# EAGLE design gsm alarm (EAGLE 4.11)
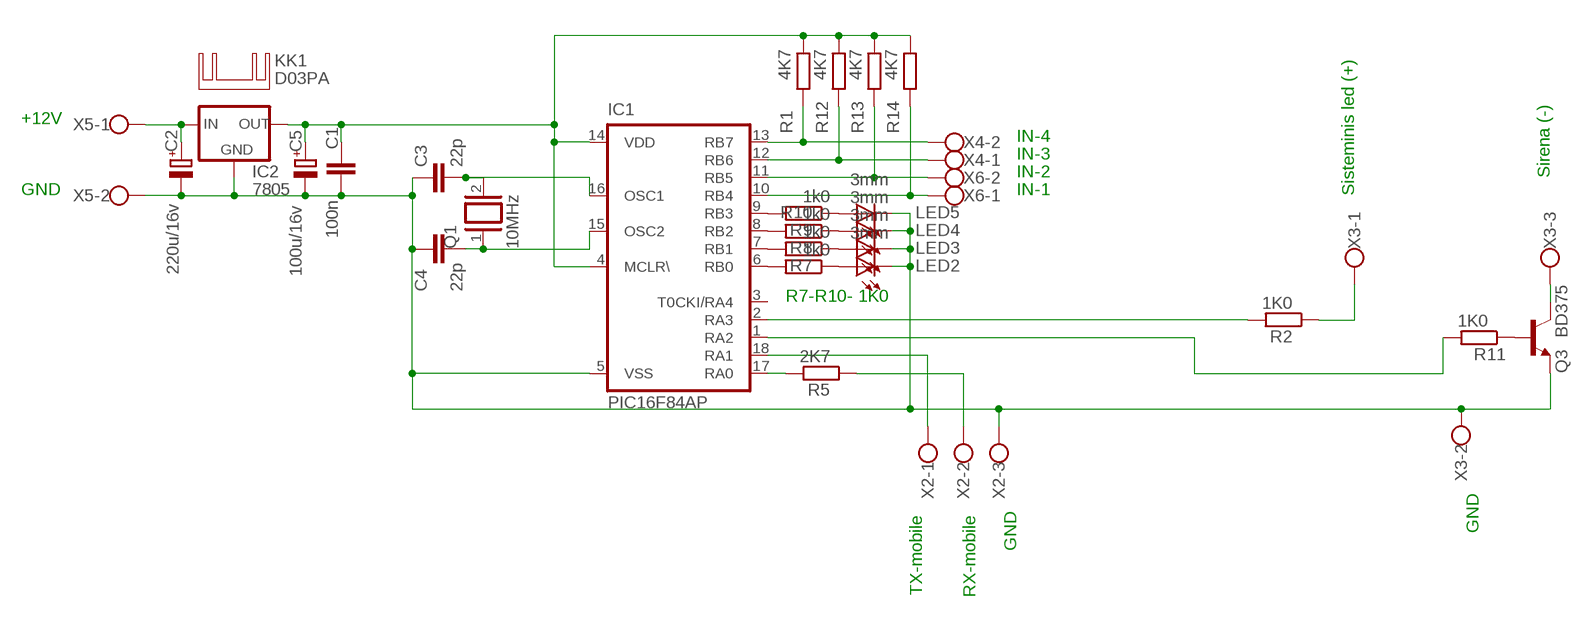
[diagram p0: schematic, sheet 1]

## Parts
C1  100n  C-EU050-045X075  [C050-045X075]
C2  220u/16v  CPOL-EUE5-10.5  [E5-10,5]
C3  22p  C-EU050-030X075  [C050-030X075]
C4  22p  C-EU050-030X075  [C050-030X075]
C5  100u/16v  CPOL-EUE5-10.5  [E5-10,5]
IC1  PIC16F84AP  [DIL18]
IC2  7805  78XXS  [78XXS]
KK1  D03PA  [D03PA]
LED2  3mm  LED3MM  [LED3MM]
LED3  3mm  LED3MM  [LED3MM]
LED4  3mm  LED3MM  [LED3MM]
LED5  3mm  LED3MM  [LED3MM]
Q1  10MHz  XTAL  [Q]
Q3  BD375  BD139  [TO126]
R1  4K7  R-EU_0207/2V  [0207/2V]
R2  1K0  R-EU_0204/7  [0204/7]
R5  2K7  R-EU_0204/7  [0204/7]
R7  1k0  R-EU_0204/7  [0204/7]
R8  1k0  R-EU_0204/7  [0204/7]
R9  1k0  R-EU_0204/7  [0204/7]
R10  1k0  R-EU_0204/7  [0204/7]
R11  1K0  R-EU_0204/7  [0204/7]
R12  4K7  R-EU_0207/2V  [0207/2V]
R13  4K7  R-EU_0207/2V  [0207/2V]
R14  4K7  R-EU_0207/2V  [0207/2V]
X2  AK300/3  [AK300/3]
X3  AK300/3  [AK300/3]
X4  AK300/2  [AK300/2]
X5  AK300/2  [AK300/2]
X6  AK300/2  [AK300/2]

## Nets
N$1: IC1.18(RA1) X2.1
N$2: R5.1 X2.2
N$3: IC1.13(RB7) R1.1 X4.2
N$4: Q3.3(B) R11.1
N$5: IC1.12(RB6) R12.1 X4.1
N$6: C1.1 C5.+ IC1.4(MCLR\) IC1.14(VDD) IC2.OUT R1.2 R12.2 R13.2 R14.2
N$7: IC1.11(RB5) R13.1 X6.2
N$8: R2.1 X3.1
N$9: Q3.2(C) X3.3
N$10: IC1.10(RB4) R14.1 X6.1
N$11: IC1.2(RA3) R2.2
N$12: IC1.6(RB0) R7.2
N$13: IC1.7(RB1) R8.2
N$14: IC1.8(RB2) R9.2
N$15: IC1.9(RB3) R10.2
N$16: LED2.A R7.1
N$17: C3.2 IC1.16(OSC1) Q1.2
N$18: C4.2 IC1.15(OSC2) Q1.1
N$21: C2.+ IC2.IN X5.1
N$28: LED3.A R8.1
N$29: C1.2 C2.- C3.1 C4.1 C5.- IC1.5(VSS) IC2.GND LED2.K(C) LED3.K(C) LED4.K(C) LED5.K(C) Q3.1(E) X2.3 X3.2 X5.2
N$30: LED4.A R9.1
N$31: LED5.A R10.1
N$34: IC1.1(RA2) R11.2
N$70: IC1.17(RA0) R5.2
Unconnected: IC1.3(T0CKI/RA4)

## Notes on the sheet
- +12V
- IN-4
- IN-3
- IN-2 | Sirena (-)
- GND | IN-1 | Sisteminis led (+)
- R7-R10- 1K0
- TX-mobile | RX-mobile
- GND
- GND

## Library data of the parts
C1 C3 C4 = rcl:C-EU: CAPACITOR, European symbol
C2 C5 = rcl:CPOL-EU: POLARIZED CAPACITOR, European symbol
IC1 = microchip:PIC16F8*: MICROCONTROLLER 8-Bit PIC16F8X Family - CMOS Flash/EEPROM Pin Compatible : PIC16F83, PIC16CR83, PIC16F84A, PIC16CR84 see also PIC16C*
IC2 = v-reg:78XXS: VOLTAGE REGULATOR
KK1 = heatsink:D03PA: HEATSINK
LED2-LED5 = led:LED: LED
Q1 = special:XTAL: CRYSTAL
Q3 = transistor-npn:BD139*: NPN Transistor
R1 R2 R5 R7-R14 = rcl:R-EU_: RESISTOR, European symbol
X2 X3 = con-ptr500+:AK300/3: CONNECTOR
X4-X6 = con-ptr500+:AK300/2: CONNECTOR

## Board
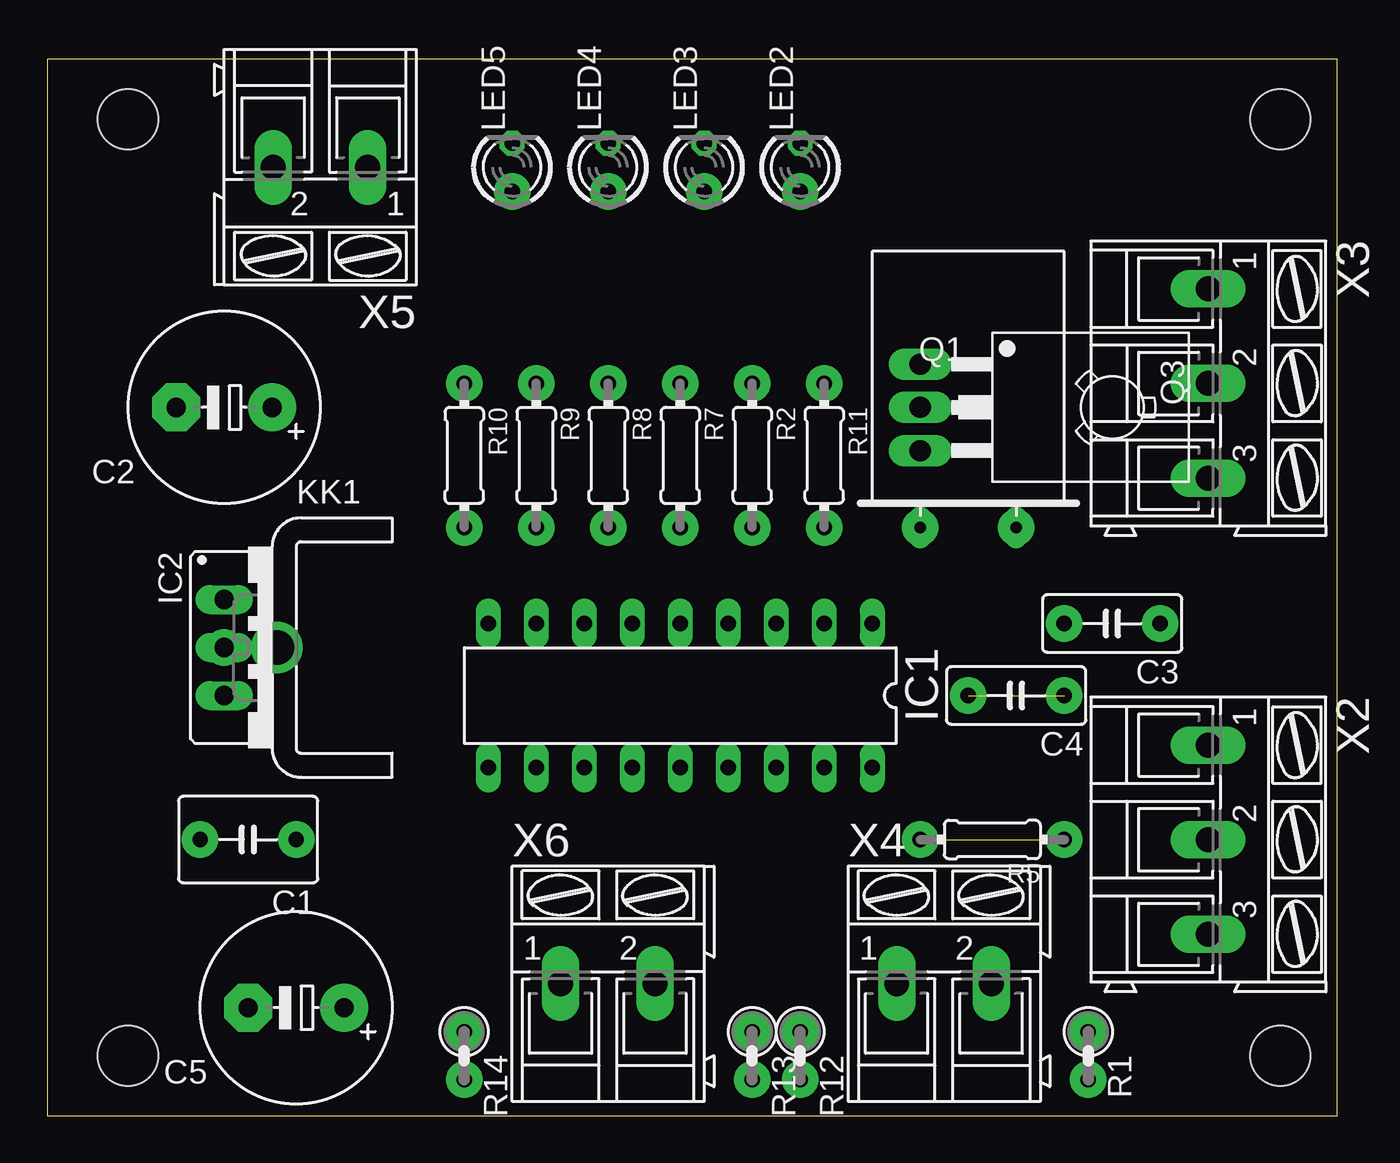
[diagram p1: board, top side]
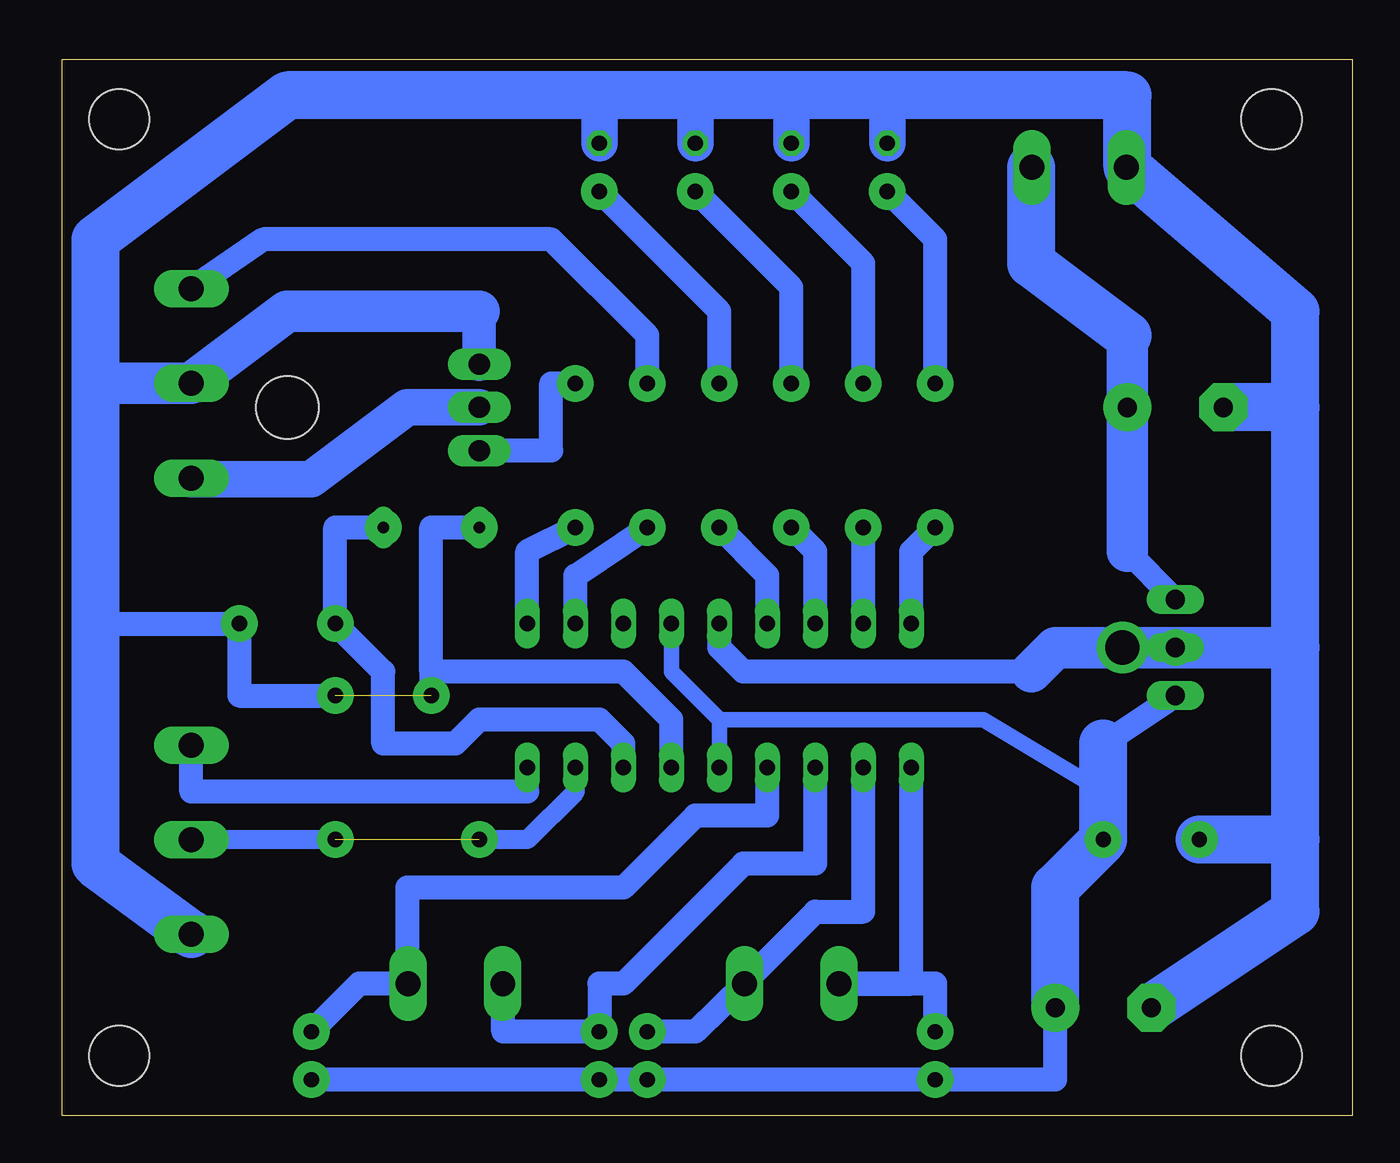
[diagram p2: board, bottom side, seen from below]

Size 68.25 x 55.87 mm. Coordinates in mm from the lower left corner, seen from the top.
Outline: 0,0 68.25,0 68.25,55.87 0,55.87 0,0
Copper layers (1*16): Top 0.035mm / dielectric 1.5mm / Bottom 0.035mm
Design rules "default": minimum track width 10mil, minimum drill 24mil, track to track 8mil, track to pad 8mil, pad to pad 8mil, via to via 8mil, smd to smd 8mil, copper to edge 40mil, drill to drill 8mil, minimum pad ring 10mil, minimum via ring 8mil, stop-mask expansion 4mil, vias tented up to drill 0mil, thermal gap 10mil
Holes 3.2 mm at 4.28,3.17 4.28,52.7 65.24,52.7 65.24,3.17

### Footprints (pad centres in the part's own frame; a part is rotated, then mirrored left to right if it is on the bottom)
C050-045X075 = drill 0.813 octagon: 1 -2.54,0; 2 2.54,0
E5-10,5 = drill 1.016 pad 2.54 round: + -2.54,0 | drill 1.016 pad 2.54 octagon: - 2.54,0
C050-030X075 = drill 0.813 octagon: 1 -2.54,0; 2 2.54,0
DIL18 = drill 0.813 long: 1 -10.16,-3.81; 2 -7.62,-3.81; 3 -5.08,-3.81; 4 -2.54,-3.81; 5 0,-3.81; 6 2.54,-3.81; 7 5.08,-3.81; 8 7.62,-3.81; 9 10.16,-3.81; 10 10.16,3.81; 11 7.62,3.81; 12 5.08,3.81; 13 2.54,3.81; 14 0,3.81; 15 -2.54,3.81; 16 -5.08,3.81; 17 -7.62,3.81; 18 -10.16,3.81
78XXS = drill 1.016 long: GND 0,-2.54; IN -2.54,-2.54; OUT 2.54,-2.54
D03PA = drill 1.803 pad 2.54 round: B 0,-1.016
LED3MM = drill 0.813 octagon: A -1.27,0; K 1.27,0
Q = drill 0.61 long: 1 -2.54,-7.62; 2 2.54,-7.62
TO126 = drill 1.118 long: 1 -2.286,-5.08; 2 0,-5.08; 3 2.286,-5.08 | hole 3.302: 0,5.08
0207/2V = drill 0.813 octagon: 1 -1.27,0; 2 1.27,0
0204/7 = drill 0.813 octagon: 1 -3.81,0; 2 3.81,0
AK300/3 = drill 1.321 long: 1 -5.004,0; 2 0,0; 3 5.004,0
AK300/2 = drill 1.321 long: 1 -2.515,0; 2 2.489,0

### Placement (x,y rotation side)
C1  10.63,14.6 180 top
C2  9.36,37.46 180 top
C3  56.35,26.03 180 top
C4  51.27,22.22 180 top
C5  13.17,5.71 180 top
IC1  33.49,22.22 180 top
IC2  11.9,24.76 270 top
KK1  13.17,24.76 270 top
LED2  39.84,50.16 90 top
LED3  34.76,50.16 90 top
LED4  29.68,50.16 90 top
LED5  24.6,50.16 90 top
Q1  48.73,38.73 0 top
Q3  51.27,37.46 270 top
R1  55.08,3.17 270 top
R2  37.3,34.92 270 top
R5  50,14.6 180 top
R7  33.49,34.92 270 top
R8  29.68,34.92 270 top
R9  25.87,34.92 270 top
R10  22.06,34.92 270 top
R11  41.11,34.92 270 top
R12  39.84,3.17 270 top
R13  37.3,3.17 270 top
R14  22.06,3.17 270 top
X2  61.43,14.6 270 top
X3  61.43,38.73 270 top
X4  47.46,6.98 0 top
X5  14.44,50.16 180 top
X6  29.68,6.98 0 top

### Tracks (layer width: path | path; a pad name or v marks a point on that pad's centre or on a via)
N$1
  Bottom 0.813: 61.43,18.41 X2.1 61.43,19.68
  Bottom 1.27: IC1.18 43.65,17.14 61.43,17.14 X2.1
N$2
  Bottom 1.016: R5.1 X2.2 R5.1
N$3
  Bottom 0.813: 50,6.98 X4.2
  Bottom 1.27: IC1.13 30.95,15.87 34.76,15.87 38.57,12.06 50,12.06 50,6.98 | X4.2 52.54,6.98 R1.1
N$4
  Bottom 1.27: Q3.3 42.38,35.17 42.38,38.73 R11.1
N$5
  Bottom 0.813: 44.92,6.98 X4.1
  Bottom 1.27: IC1.12 28.41,13.33 32.22,13.33 38.57,6.98 39.84,6.98 R12.1 44.92,4.44 44.92,6.98
N$6
  Bottom 0.813: IC1.4 36.03,23.49 33.49,20.95 | 33.49,20.95 19.52,20.95 13.17,17.14 | 33.49,20.95 IC1.14
  Bottom 1.27: 13.17,19.68 IC2.OUT | C5.+ 15.71,1.9 R14.2 R13.2 R12.2 R1.2
  Bottom 2.54: C5.+ 15.71,12.06 C1.1 13.17,17.14 13.17,19.68
N$7
  Bottom 0.813: X6.2 32.22,6.98
  Bottom 1.27: 32.22,6.98 28.41,10.79 25.87,10.79 IC1.11 | X6.2 34.76,4.44 R13.1
N$8
  Bottom 1.27: R2.1 37.3,41.27 42.38,46.35 57.62,46.35 X3.1
N$9
  Bottom 0.813: 61.43,33.65 X3.3
  Bottom 1.93: Q3.2 50,37.46 55.08,33.65 61.43,33.65
N$10
  Bottom 1.27: R14.1 22.06,6.98 X6.1 23.33,6.98 IC1.10
N$11
  Bottom 1.27: IC1.2 41.11,28.57 R2.2
N$12
  Bottom 1.27: R7.2 30.95,28.57 IC1.6
N$13
  Bottom 1.27: R8.2 28.41,29.84 IC1.7
N$14
  Bottom 1.27: IC1.8 R9.2
N$15
  Bottom 1.27: R10.2 23.33,29.84 IC1.9
N$16
  Bottom 1.27: R7.1 33.49,42.54 LED2.A
N$17
  Bottom 1.27: Q1.2 53.81,31.11 C3.2 51.27,23.49 51.27,19.68 47.46,19.68 46.19,20.95 39.84,20.95 38.57,19.68 IC1.16
N$18
  Bottom 1.27: 48.73,23.49 C4.2 | Q1.1 48.73,31.11 48.73,23.49 | 48.73,23.49 38.57,23.49 36.03,20.95 IC1.15
N$20  (via drill 0.5 pad 1.78)
  other vias: 22.06,38.73
N$21
  Bottom 0.406: 16.98,50.16 X5.1
  Bottom 1.27: IC2.IN 11.9,29.84
  Bottom 2.184: 11.9,29.84 C2.+ 11.9,41.27
  Bottom 2.54: 11.9,41.27 16.98,45.08 16.98,50.16
N$22  (via drill 0.5 pad 1.93)
  other vias: 29.68,48.89
N$23  (via drill 0.5 pad 1.93)
  other vias: 24.6,48.89
N$24  (via drill 0.5 pad 1.93)
  other vias: 34.76,48.89
N$25  (via drill 0.5 pad 1.93)
  other vias: 29.68,38.73
N$26  (via drill 0.5 pad 1.93)
  other vias: 39.84,48.89
N$27  (via drill 0.5 pad 1.93)
  other vias: 33.49,38.73
N$28
  Bottom 1.27: R8.1 29.68,43.81 LED3.A
N$29
  Bottom 0.406: 11.9,50.16 X5.2
  Bottom 0.813: X3.2 61.43,38.48
  Bottom 1.27: IC1.5 33.49,24.76 32.22,23.49 16.98,23.49 | 58.89,22.22 C4.1 58.89,22.22 | 58.89,22.22 C3.1 66.51,26.03
  Bottom 1.778: 46.19,42.54 Q3.1
  Bottom 1.93: 39.84,53.97 LED2.K | 34.76,53.97 LED3.K | 29.68,53.97 LED4.K | 24.6,53.97 LED5.K
  Bottom 2.184: 3.01,24.76 IC2.GND 15.71,24.76 16.98,23.49 | 66.51,38.73 X3.2 56.35,42.54 46.19,42.54
  Bottom 2.54: 3.01,37.46 3.01,42.54 11.9,50.16 11.9,53.97 24.6,53.97 29.68,53.97 34.76,53.97 39.84,53.97 56.35,53.97 66.51,46.35 66.51,38.73 66.51,26.03 66.51,13.33 X2.3 | 3.01,37.46 C2.- | 3.01,37.46 3.01,24.76 3.01,14.6 | 3.01,14.6 3.01,10.79 C5.- | 3.01,14.6 C1.2
N$30
  Bottom 1.27: R9.1 25.87,45.08 LED4.A
N$31
  Bottom 1.27: R10.1 22.06,46.35 LED5.A
N$32  (via drill 0.5 pad 1.93)
  other vias: 22.06,38.73
N$33  (via drill 0.5 pad 1.93)
  other vias: 37.3,38.73
N$34
  Bottom 1.27: IC1.1 43.65,29.84 R11.2
N$35  (via drill 0.5 pad 1.93)
  other vias: 41.11,31.11
N$36  (via drill 0.5 pad 1.93)
  other vias: 33.49,31.11
N$37  (via drill 0.5 pad 1.93)
  other vias: 41.11,38.73
N$38  (via drill 0.5 pad 1.93)
  other vias: 25.87,38.73
N$39  (via drill 0.5 pad 1.93)
  other vias: 25.87,31.11
N$40  (via drill 0.5 pad 1.93)
  other vias: 51.27,31.11
N$41  (via drill 0.5 pad 1.93)
  other vias: 22.06,31.11
N$42  (via drill 0.5 pad 1.93)
  other vias: 29.68,31.11
N$43  (via drill 0.5 pad 1.93)
  other vias: 37.3,31.11
N$44  (via drill 0.5 pad 1.93)
  other vias: 46.19,31.11
N$45  (via drill 0.5 pad 1.93)
  other vias: 6.82,37.46
N$46  (via drill 0.5 pad 1.93)
  other vias: 39.84,4.44
N$48  (via drill 0.5 pad 1.93)
  other vias: 58.89,26.03
N$49  (via drill 0.5 pad 1.93)
  other vias: 11.9,37.46
N$50  (via drill 0.5 pad 1.93)
  other vias: 15.71,5.71
N$51  (via drill 0.5 pad 1.93)
  other vias: 13.17,14.6
N$52  (via drill 0.5 pad 1.93)
  other vias: 9.36,24.76
N$53  (via drill 0.5 pad 1.93)  (1 unrouted)
  other vias: 53.81,14.6 46.19,14.6
N$54  (via drill 0.5 pad 1.93)
  other vias: 53.81,26.03
N$55  (via drill 0.5 pad 1.93)  (1 unrouted)
  other vias: 53.81,22.22 53.81,22.22 53.81,22.22 48.73,22.22
N$57  (via drill 0.5 pad 1.93)
  other vias: 10.63,5.71
N$58  (via drill 0.5 pad 1.93)
  other vias: 22.06,4.44
N$59  (via drill 0.5 pad 1.93)
  other vias: 39.84,1.9
N$60  (via drill 0.5 pad 1.93)
  other vias: 22.06,1.9
N$61  (via drill 0.5 pad 1.93)
  other vias: 8.09,14.6
N$62  (via drill 0.5 pad 1.93)
  other vias: 55.08,4.44
N$63  (via drill 0.5 pad 1.93)
  other vias: 55.08,1.9
N$65  (via drill 0.5 pad 1.93)
  other vias: 37.3,4.44
N$66  (via drill 0.5 pad 1.93)
  other vias: 37.3,1.9
N$70
  Bottom 1.016: 43.65,14.6 41.11,17.14 IC1.17 | 43.65,14.6 R5.2 43.65,14.6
